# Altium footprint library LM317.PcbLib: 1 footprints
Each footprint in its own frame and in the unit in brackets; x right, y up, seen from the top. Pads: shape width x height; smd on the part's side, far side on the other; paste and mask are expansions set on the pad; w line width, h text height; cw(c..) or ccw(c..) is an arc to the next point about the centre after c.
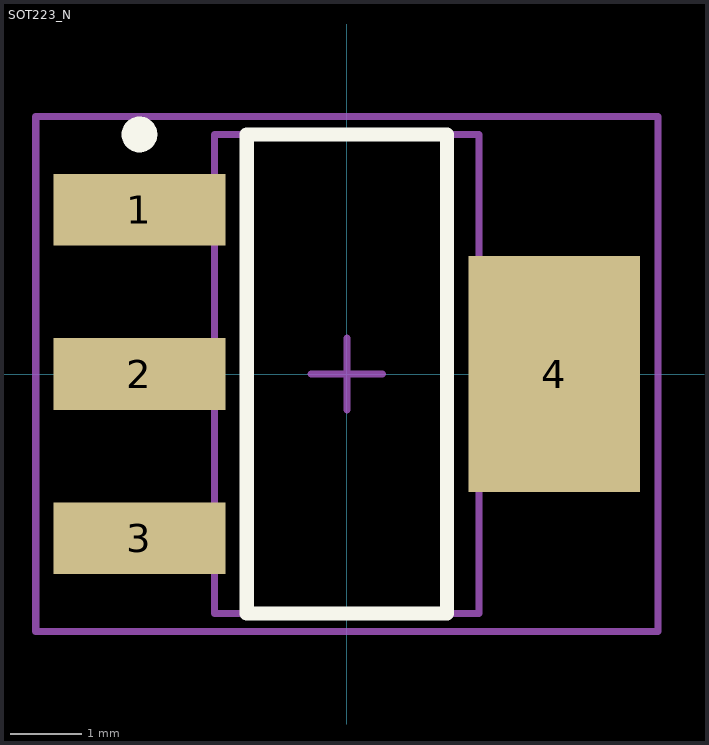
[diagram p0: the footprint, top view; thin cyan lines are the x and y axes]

## SOT223_N [mm] "SOT223, 4-Leads, Body 6.5x3.5mm, Pitch 2.3mm, Lead Span 7mm, IPC Medium Density"
height 1.7
pads (4):
  rect 2.4x1 smd: 1(-2.9,2.3) 2(-2.9,0) 3(-2.9,-2.3)
  rect 2.4x3.3 smd: 4(2.9,0)
Top Overlay:
  circle w0.25: c-2.9,3.35 r0.125
  lines w0.2: -1.4,-3.35 1.4,-3.35 1.4,3.35 -1.4,3.35 -1.4,-3.35
Mechanical 13:
  lines w0.1: -1.85,-3.35 1.85,-3.35 1.85,3.35 -1.85,3.35 -1.85,-3.35
Mechanical 15:
  lines w0.1: -0.5,0 0.5,0 ; 0,-0.5 0,0.5 ; -4.35,-3.6 4.35,-3.6 4.35,3.6 -4.35,3.6 -4.35,-3.6
3D body: height 1.7, standoff 0, extent -1.85,-3.35 1.85,3.35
